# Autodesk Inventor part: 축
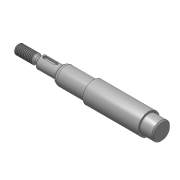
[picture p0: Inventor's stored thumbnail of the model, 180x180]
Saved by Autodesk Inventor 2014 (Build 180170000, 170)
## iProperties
Created: 2015-11
Part Number: 축
Material: 강철, 연강
Document SubType Name: Modeling
Designer: mduedu
Density: 1 g/cm^3
Appearance: 강철
Author: mduedu
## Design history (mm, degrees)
sketch "스케치1"
  geometry: L1 (-86, 0)-(86, 0); L2 (-86, 0)-(-86, 4); L3 (-86, 4)-(-70.732, 4); L4 (-70.732, 4)-(-69, 3); L5 (-69, 3)-(-67, 3); L6 (-67, 3)-(-67, 5); L7 (-67, 5)-(-49, 5); L8 (-49, 5)-(-49, 6.55); L9 (-47.355, 7.5)-(-23, 7.5); L10 (-23, 7.5)-(-23, 9); L11 (0, 0)-(0, 9); L12 (86, 4)-(70.732, 4); L13 (70.732, 4)-(69, 3); L14 (69, 3)-(67, 3); L15 (67, 3)-(67, 5); L16 (67, 5)-(49, 5); L17 (23, 7.5)-(23, 9); L18 (86, 0)-(86, 4); L19 (-23, 9)-(23, 9); L20 (-49, 6.55)-(-47.355, 7.5); L21 (47.355, 7.5)-(23, 7.5); L22 (49, 6.55)-(47.355, 7.5); L23 (49, 5)-(49, 6.55); 1 further point
  constraints: 46 end point, 10 symmetric about line, 6 perpendicular, 5 parallel, 2 midpoint, 1 coincident, 1 horizontal
  dimensions: "d0" = 172 distance of L1.start L1.end (derived); "d1" = 8 diameter of L3 L1; "d2" = 30 deg angle of L4 L5; "d3" = 6 diameter of L5 L1; "d4" = 10 diameter of L7 L1; "d5" = 15 diameter of L9 L1; "d6" = 18 diameter of L19 L1; "d8" = 18 distance of L6.end L7.end; "d9" = 46 distance of L10.end L17.end; "d10" = 2 distance of L4.end L5.end; "d11" = 17 distance from line of L4.end L2; "d16" = 13.1 diameter of L8.end L1; "d17" = 30 deg angle of L20 L9; "d18" = 26 distance between parallel lines of L10 L8
revolve "회전1" sketch "스케치1" stored, may be unused: angle "d12" = 90 deg
chamfer "모따기1" distance "d13" = 1; stored, may be unused: second distance "d14" = 2, angle "d15" = 45 deg
fillet "모깎기3" dims "d35" = 4
node "작업 평면1"
sketch "스케치2" dims "d23" = 12
  geometry: L1 (-5.5, 1.5)-(3.5, 1.5); L2 (3.5, 1.5)-(3.5, -1.5); L3 (3.5, -1.5)-(-5.5, -1.5); L4 (-5.5, -1.5)-(-5.5, 1.5); L5 (-9, -4)-(-9, 4) reference; 3 further points
  constraints: 8 end point, 2 midpoint, 2 parallel, 2 vertical alignment, 1 horizontal, 1 perpendicular, 4 other
  dimensions: "d21" = 3 distance between parallel lines of L3 L1; "d24" = 2 dimension on L5
extrude "돌출1" cut sketch "스케치2" distance "d25" = 1.8; taper "d26" = 0 deg
feature "스레드1" dims "d27" = 10, "d28" = 0
feature "스레드2" dims "d29" = 10, "d30" = 0
chamfer "모따기2" distance "d31" = 1; stored, may be unused: second distance "d32" = 2, angle "d33" = 45 deg
fillet "모깎기2" dims "d34" = 0.3
node "작업 평면2"
sketch "스케치3"
  geometry: C1 r 7.5 at (0, 0) reference; 1 further point
extrude "돌출2" cut sketch "스케치3" stored distance "d37" = 10; taper "d38" = 0 deg
chamfer "모따기3" distance "d39" = 1; stored, may be unused: second distance "d40" = 2, angle "d41" = 45 deg
node "솔리드1"
mirror "대칭1"
node "절단 모서리 투영1"
other parameters: "d36" = 11
